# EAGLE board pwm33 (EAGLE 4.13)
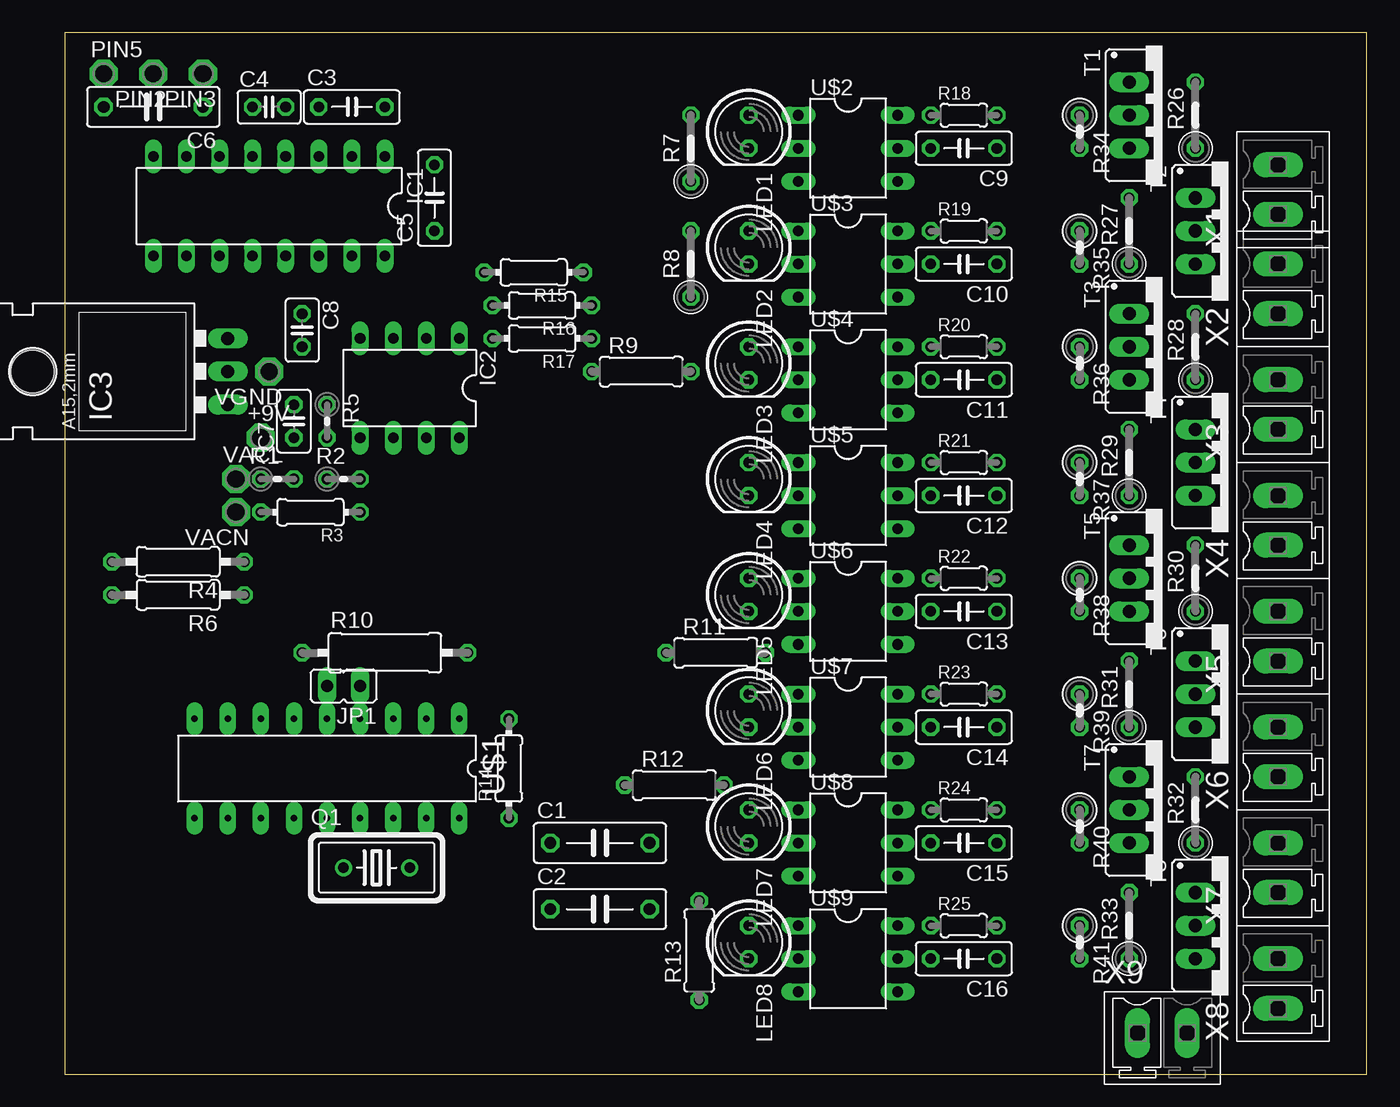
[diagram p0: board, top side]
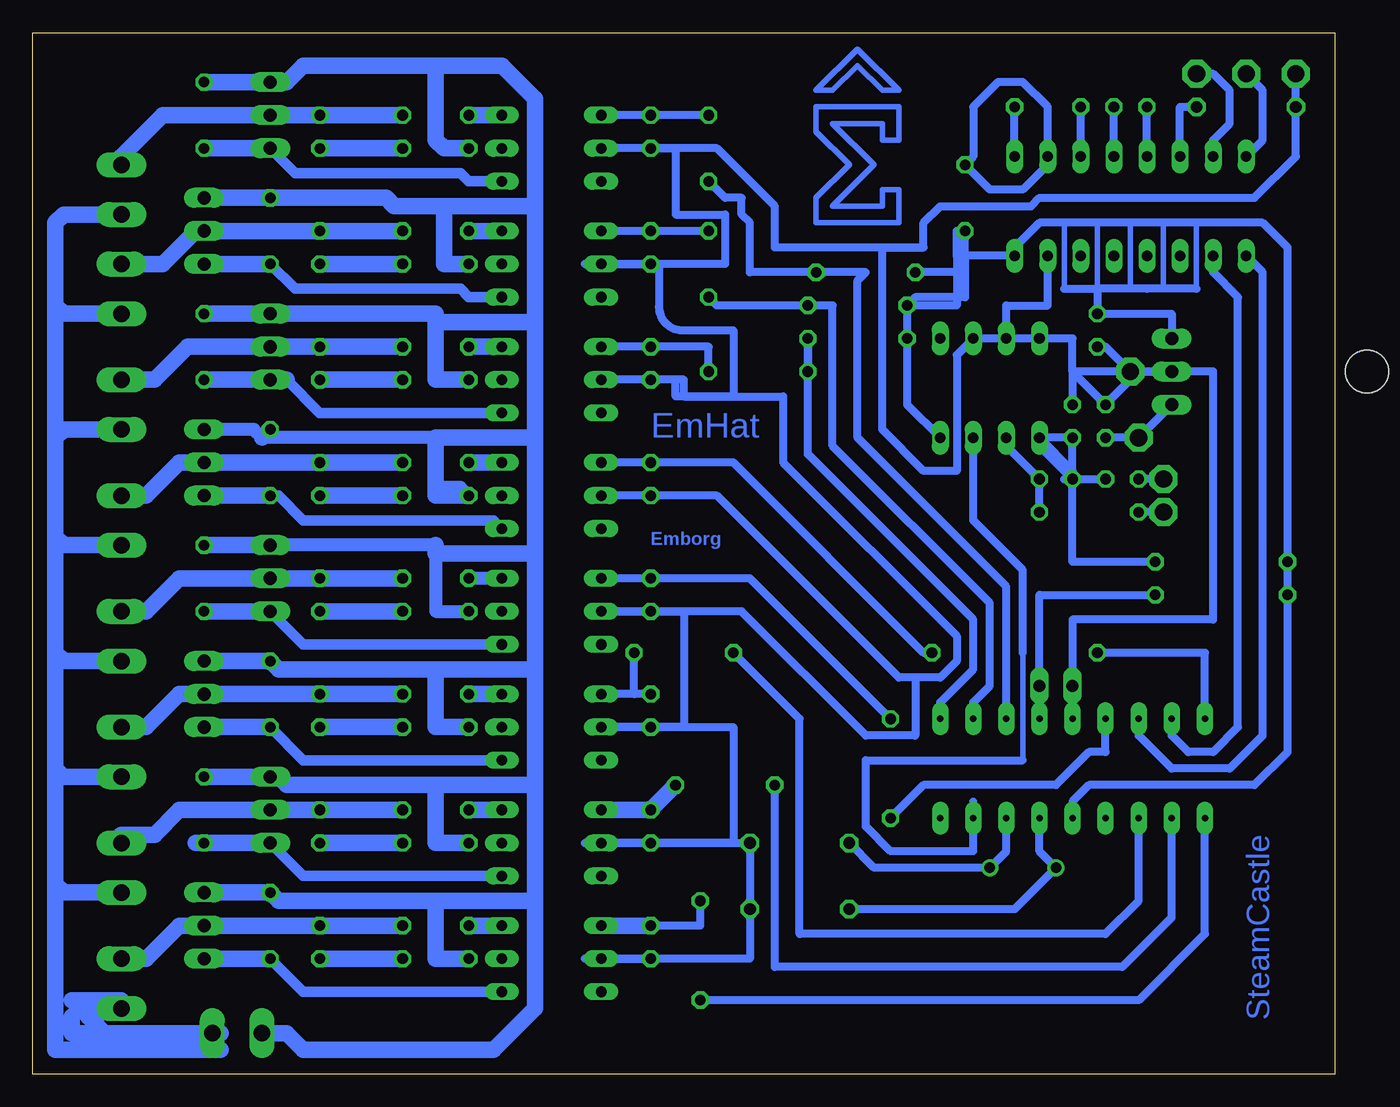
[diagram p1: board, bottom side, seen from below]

Size 100 x 80 mm. Coordinates in mm from the lower left corner, seen from the top.
Outline: 0,0 100,0 100,80 0,80 0,0
Copper layers (1*16): Top 0.035mm / dielectric 1.5mm / Bottom 0.035mm
Design rules "default": minimum track width 10mil, minimum drill 16mil, track to track 8mil, track to pad 8mil, pad to pad 8mil, via to via 8mil, smd to smd 8mil, copper to edge 40mil, drill to drill 8mil, minimum pad ring 10mil, minimum via ring 8mil, stop-mask expansion 4mil, vias tented up to drill 0mil, thermal gap 10mil

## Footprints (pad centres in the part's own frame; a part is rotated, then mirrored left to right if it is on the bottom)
P1-13 = drill 1.321 pad 2.159 octagon: 1 0,0
C075-032X103 = drill 0.914 octagon: 1 -3.81,0; 2 3.81,0
C050-025X075 = drill 0.813 octagon: 1 -2.54,0; 2 2.54,0
C025-025X050 = drill 0.813 octagon: 1 -1.27,0; 2 1.27,0
DIL16 = drill 0.813 long: 1 -8.89,-3.81; 2 -6.35,-3.81; 3 -3.81,-3.81; 4 -1.27,-3.81; 5 1.27,-3.81; 6 3.81,-3.81; 7 6.35,-3.81; 8 8.89,-3.81; 9 8.89,3.81; 10 6.35,3.81; 11 3.81,3.81; 12 1.27,3.81; 13 -1.27,3.81; 14 -3.81,3.81; 15 -6.35,3.81; 16 -8.89,3.81
DIL08 = drill 0.813 long: 1 -3.81,-3.81; 2 -1.27,-3.81; 3 1.27,-3.81; 4 3.81,-3.81; 5 3.81,3.81; 6 1.27,3.81; 7 -1.27,3.81; 8 -3.81,3.81
78XXL = drill 1.016 long: GND 0,-3.81; IN -2.54,-3.81; OUT 2.54,-3.81 | hole 3.302: 0,11.176
JP1 = drill 0.914 long: 1 0,-1.27; 2 0,1.27
LED5MM = drill 0.813 octagon: A -1.27,0; K 1.27,0
HC18U-V = drill 0.813 round: 1 -2.54,0; 2 2.54,0
0204V = drill 0.813 octagon: 1 -1.27,0; 2 1.27,0
0204/7 = drill 0.813 octagon: 1 -3.81,0; 2 3.81,0
0207/10 = drill 0.813 octagon: 1 -5.08,0; 2 5.08,0
0207/5V = drill 0.813 octagon: 1 -2.54,0; 2 2.54,0
0207/7 = drill 0.813 octagon: 1 -3.81,0; 2 3.81,0
0309/12 = drill 0.813 octagon: 1 -6.35,0; 2 6.35,0
0204/5 = drill 0.813 octagon: 1 -2.54,0; 2 2.54,0
0207/2V = drill 0.813 octagon: 1 -1.27,0; 2 1.27,0
TO220DS = drill 1.016 long: A1 -2.54,-2.54; A2 0,-2.54; G 2.54,-2.54
DIL18 = drill 0.5 pad 1.27 long: 1 -10.16,-3.81; 2 -7.62,-3.81; 3 -5.08,-3.81; 4 -2.54,-3.81; 5 0,-3.81; 6 2.54,-3.81; 7 5.08,-3.81; 8 7.62,-3.81; 9 10.16,-3.81; 10 10.16,3.81; 11 7.62,3.81; 12 5.08,3.81; 13 2.54,3.81; 14 0,3.81; 15 -2.54,3.81; 16 -5.08,3.81; 17 -7.62,3.81; 18 -10.16,3.81
DIL06 = drill 0.813 long: 1 -2.54,-3.81; 2 0,-3.81; 3 2.54,-3.81; 4 2.54,3.81; 5 0,3.81; 6 -2.54,3.81
MCV2 = drill 1.27 pad 1.905 long: 1 -1.905,0; 2 1.905,0

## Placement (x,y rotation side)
+9V  PTR1PAD1-13  [P1-13]  15.08,48.89 0 top
C1  20pF  [C075-032X103]  41.11,17.77 0 top
C2  20pF  [C075-032X103]  41.11,12.7 0 top
C3  1uF  [C050-025X075]  22.06,74.29 0 top
C4  1uF  [C025-025X050]  15.71,74.29 0 top
C5  1uF  [C050-025X075]  28.41,67.3 90 top
C6  1uF  [C075-032X103]  6.82,74.29 180 top
C7  1uF  [C025-025X050]  17.61,50.16 90 top
C8  1uF  [C025-025X050]  18.25,57.15 270 top
C9  0,01uF_400V  [C050-025X075]  69.05,71.11 180 top
C10  0,01uF_400V  [C050-025X075]  69.05,62.23 180 top
C11  0,01uF_400V  [C050-025X075]  69.05,53.34 180 top
C12  0,01uF_400V  [C050-025X075]  69.05,44.45 180 top
C13  0,01uF_400V  [C050-025X075]  69.05,35.55 180 top
C14  0,01uF_400V  [C050-025X075]  69.05,26.66 180 top
C15  0,01uF_400V  [C050-025X075]  69.05,17.77 180 top
C16  0,01uF_400V  [C050-025X075]  69.05,8.89 180 top
IC1  MAX232  [DIL16]  15.71,66.67 180 top
IC2  LM358N  [DIL08]  26.5,52.7 180 top
IC3  [78XXL]  8.73,53.97 90 top
JP1  [JP1]  21.42,29.84 90 top
LED1  [LED5MM]  52.54,72.38 270 top
LED2  [LED5MM]  52.54,63.5 270 top
LED3  [LED5MM]  52.54,54.61 270 top
LED4  [LED5MM]  52.54,45.72 270 top
LED5  [LED5MM]  52.54,36.83 270 top
LED6  [LED5MM]  52.54,27.93 270 top
LED7  [LED5MM]  52.54,19.04 270 top
LED8  [LED5MM]  52.54,10.16 270 top
PIN2  PTR1PAD1-13  [P1-13]  6.82,76.83 180 top
PIN3  PTR1PAD1-13  [P1-13]  10.63,76.83 180 top
PIN5  PTR1PAD1-13  [P1-13]  3.01,76.83 0 top
Q1  20Mhz  [HC18U-V]  23.96,15.87 0 top
R1  Aohm  [0204V]  16.34,45.72 0 top
R2  Bohm  [0204V]  21.42,45.72 0 top
R3  Aohm  [0204/7]  18.88,43.18 180 top
R4  5K  [0207/10]  8.73,39.37 180 top
R5  5K  [0204V]  20.15,50.16 270 top
R6  10K  [0207/10]  8.73,36.83 180 top
R7  240ohm  [0207/5V]  48.09,71.11 90 top
R8  240ohm  [0207/5V]  48.09,62.23 90 top
R9  240ohm  [0207/7]  44.28,53.97 0 top
R10  240ohm  [0309/12]  24.6,32.38 0 top
R11  240ohm  [0207/7]  50,32.38 0 top
R12  240ohm  [0207/7]  46.82,22.22 0 top
R13  240ohm  [0207/7]  48.73,9.52 90 top
R14  240ohm  [0204/7]  34.12,23.49 90 top
R15  10K  [0204/7]  36.03,61.59 180 top
R16  10K  [0204/7]  36.66,59.05 180 top
R17  10K  [0204/7]  36.66,56.51 180 top
R18  360ohm  [0204/5]  69.05,73.66 0 top
R19  360ohm  [0204/5]  69.05,64.77 0 top
R20  360ohm  [0204/5]  69.05,55.88 0 top
R21  360ohm  [0204/5]  69.05,46.98 0 top
R22  360ohm  [0204/5]  69.05,38.1 0 top
R23  360ohm  [0204/5]  69.05,29.2 0 top
R24  360ohm  [0204/5]  69.05,20.31 0 top
R25  360ohm  [0204/5]  69.05,11.43 0 top
R26  330ohm  [0207/5V]  86.83,73.66 90 top
R27  330ohm  [0207/5V]  81.75,64.77 90 top
R28  330ohm  [0207/5V]  86.83,55.88 90 top
R29  330ohm  [0207/5V]  81.75,46.98 90 top
R30  330ohm  [0207/5V]  86.83,38.1 90 top
R31  330ohm  [0207/5V]  81.75,29.2 90 top
R32  330ohm  [0207/5V]  86.83,20.31 90 top
R33  330ohm  [0207/5V]  81.75,11.43 90 top
R34  39ohm  [0207/2V]  77.94,72.38 270 top
R35  39ohm  [0207/2V]  77.94,63.5 270 top
R36  39ohm  [0207/2V]  77.94,54.61 270 top
R37  39ohm  [0207/2V]  77.94,45.72 270 top
R38  39ohm  [0207/2V]  77.94,36.83 270 top
R39  39ohm  [0207/2V]  77.94,27.93 270 top
R40  39ohm  [0207/2V]  77.94,19.04 270 top
R41  39ohm  [0207/2V]  77.94,10.16 270 top
T1  TIC225S  [TO220DS]  84.29,73.66 270 top
T2  TIC225S  [TO220DS]  89.37,64.77 270 top
T3  TIC225S  [TO220DS]  84.29,55.88 270 top
T4  TIC225S  [TO220DS]  89.37,46.98 270 top
T5  TIC225S  [TO220DS]  84.29,38.1 270 top
T6  TIC225S  [TO220DS]  89.37,29.2 270 top
T7  TIC225S  [TO220DS]  84.29,20.31 270 top
T8  TIC225S  [TO220DS]  89.37,11.43 270 top
U$1  PIC16F627I/P  [DIL18]  20.15,23.49 180 top
U$2  MOC3021M  [DIL06]  60.16,71.11 270 top
U$3  MOC3021M  [DIL06]  60.16,62.23 270 top
U$4  MOC3021M  [DIL06]  60.16,53.34 270 top
U$5  MOC3021M  [DIL06]  60.16,44.45 270 top
U$6  MOC3021M  [DIL06]  60.16,35.55 270 top
U$7  MOC3021M  [DIL06]  60.16,26.66 270 top
U$8  MOC3021M  [DIL06]  60.16,17.77 270 top
U$9  MOC3021M  [DIL06]  60.16,8.89 270 top
VACL  PTR1PAD1-13  [P1-13]  13.17,45.72 0 top
VACN  PTR1PAD1-13  [P1-13]  13.17,43.18 180 top
VGND  PTR1PAD1-13  [P1-13]  15.71,53.97 180 top
X1  MCV2  [MCV2]  93.18,67.94 90 top
X2  MCV2  [MCV2]  93.18,60.32 90 top
X3  MCV2  [MCV2]  93.18,51.43 90 top
X4  MCV2  [MCV2]  93.18,42.54 90 top
X5  MCV2  [MCV2]  93.18,33.65 90 top
X6  MCV2  [MCV2]  93.18,24.76 90 top
X7  MCV2  [MCV2]  93.18,15.87 90 top
X8  MCV2  [MCV2]  93.18,6.98 90 top
X9  MCV2  [MCV2]  84.29,3.17 0 top

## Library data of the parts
+9V PIN2 PIN3 PIN5 VACL VACN VGND = testpad
C1-C16 R1-R41 = rcl
IC1 = maxim
IC2 = linear
IC3 = v-reg
JP1 = jumper
LED1-LED8 = led
Q1 = crystal
T1-T8 = triac
U$1 = microchip-4
U$2-U$9 = optocoupler
X1-X9 = con-phoenix-381_l

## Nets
N$1: C1.1 Q1.2 U$1.16
N$2: C2.1 Q1.1 U$1.15
N$3: +9V.1 C7.1 IC3.IN
N$4: C4.1 IC1.5
N$5: C4.2 IC1.4
N$6: C3.1 IC1.3
N$7: C3.2 IC1.1
N$8: C5.2 IC1.2
N$9: C6.1 IC1.6
N$10: R9.1 R17.1 U$1.1
N$11: IC2.6 R2.2 R3.1
N$12: IC2.7 U$1.17
N$13: IC2.5 R1.2 R2.1 R4.1 R5.2
N$14: IC1.9 U$1.7
N$15: IC1.10 U$1.8
N$16: R1.1 VACL.1
N$17: R3.2 VACN.1
N$18: R8.1 R16.1 U$1.2
N$19: R7.1 R15.1 U$1.3
N$20: IC1.8 PIN2.1
N$21: IC1.7 PIN3.1
N$22: R14.1 U$1.6
N$23: R10.1 U$1.9
N$24: R11.1 U$1.12
N$25: R12.1 U$1.11
N$26: R13.1 U$1.10
N$27: LED1.A R7.2 U$2.1
N$28: LED2.A R8.2 U$3.1
N$29: LED3.A R9.2 U$4.1
N$30: LED4.A R10.2 U$5.1
N$31: LED5.A R14.2 U$6.1
N$32: LED6.A R11.2 U$7.1
N$33: LED7.A R12.2 U$8.1
N$34: LED8.A R13.2 U$9.1
N$35: X1.1 X2.1 X3.1 X4.1 X5.1 X6.1 X7.1 X8.1 X9.2
N$36: JP1.1 R6.1 U$1.4
N$37: C9.1 R34.2
N$38: R18.1 U$2.6
N$39: R19.1 U$3.6
N$40: R20.1 U$4.6
N$41: R21.1 U$5.6
N$42: R22.1 U$6.6
N$43: R23.1 U$7.6
N$44: R24.1 U$8.6
N$45: R25.1 U$9.6
N$46: R18.2 R34.1 T1.A2 X1.2
N$47: R19.2 R35.1 T2.A2 X2.2
N$48: R20.2 R36.1 T3.A2 X3.2
N$49: R21.2 R37.1 T4.A2 X4.2
N$50: R22.2 R38.1 T5.A2 X5.2
N$51: R23.2 R39.1 T6.A2 X6.2
N$52: R24.2 R40.1 T7.A2 X7.2
N$53: R25.2 R41.1 T8.A2 X8.2
N$54: R26.1 T1.G U$2.4
N$55: R27.1 T2.G U$3.4
N$56: R28.1 T3.G U$4.4
N$57: R29.1 T4.G U$5.4
N$58: R30.1 T5.G U$6.4
N$59: R31.1 T6.G U$7.4
N$60: R32.1 T7.G U$8.4
N$61: R33.1 T8.G U$9.4
N$62: C9.2 C10.2 C11.2 C12.2 C13.2 C14.2 C15.2 C16.2 R26.2 R27.2 R28.2 R29.2 R30.2 R31.2 R32.2 R33.2 T1.A1 T2.A1 T3.A1 T4.A1 T5.A1 T6.A1 T7.A1 T8.A1 X9.1
N$70: C10.1 R35.2
N$71: C11.1 R36.2
N$72: C12.1 R37.2
N$73: C13.1 R38.2
N$74: C14.1 R39.2
N$75: C15.1 R40.2
N$76: C16.1 R41.2
V+: C5.1 C8.1 IC1.16 IC2.8 IC3.OUT R4.2 R6.2 R15.2 R16.2 R17.2 U$1.14
V-: C1.2 C2.2 C6.2 C7.2 C8.2 IC1.15 IC2.2 IC2.3 IC2.4 IC3.GND JP1.2 LED1.K LED2.K LED3.K LED4.K LED5.K LED6.K LED7.K LED8.K PIN5.1 R5.1 U$1.5 U$2.2 U$3.2 U$4.2 U$5.2 U$6.2 U$7.2 U$8.2 U$9.2 VGND.1

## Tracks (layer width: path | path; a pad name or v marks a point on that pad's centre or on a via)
N$1
  Bottom 0.61: U$1.16 25.23,17.14 Q1.2 35.39,15.87 C1.1
N$2
  Bottom 0.61: C2.1 24.6,12.7 Q1.1 22.7,17.14 U$1.15
N$3
  Bottom 0.61: C7.1 +9V.1 IC3.IN
N$4
  Bottom 0.61: IC1.5 C4.1
N$5
  Bottom 0.61: IC1.4 C4.2
N$6
  Bottom 0.61: IC1.3 C3.1
N$7
  Bottom 0.61: IC1.1 C3.2
N$8
  Bottom 0.61: 23.96,67.94 26.5,67.94 C5.2 27.77,70.48 27.77,74.29 25.87,76.19 23.96,76.19 22.06,74.29 IC1.2 22.06,69.84 23.96,67.94
N$9
  Bottom 0.61: C6.1 11.9,74.29 IC1.6
N$10
  Bottom 0.61: R9.1 R17.1 40.48,47.62 27.77,34.92 27.77,31.11 30.31,28.57 U$1.1
N$11
  Bottom 0.61: R3.1 R2.2 25.23,48.26 IC2.6
N$12
  Bottom 0.406: 23.96,24.12 23.96,32.38
  Bottom 0.61: IC2.7 27.77,42.54 23.96,38.73 23.96,32.38 | 27.77,20.95 U$1.17 27.77,17.14 34.12,17.14 36.03,19.04 36.03,24.12 23.96,24.12
N$13
  Bottom 0.61: IC2.5 R5.2 20.15,46.35 | IC2.5 22.7,48.26 R2.1 | R4.1 20.15,39.37 R2.1 | R2.1 R1.2 | R2.1 20.79,45.72 | 20.15,46.35 IC2.5 | R2.1 20.15,46.35
N$14
  Bottom 0.61: U$1.7 15.08,26.03 12.54,23.49 8.09,23.49 5.55,26.03 5.55,61.59 IC1.9
N$15
  Bottom 0.61: U$1.8 12.54,26.03 11.27,24.76 9.36,24.76 7.46,26.66 7.46,59.69 9.36,61.59 IC1.10
N$16
  Bottom 0.61: VACL.1 R1.1
N$17
  Bottom 0.61: VACN.1 R3.2
N$18
  Bottom 0.61: R8.1 47.46,59.05 R16.1 38.57,59.05 38.57,48.26 26.5,36.19 26.5,29.84 27.77,28.57 U$1.2
N$19
  Bottom 0.61: U$1.3 25.23,37.46 36.66,48.89 36.66,60.96 36.03,61.59 R15.1 44.92,61.59 44.92,65.4 45.55,66.03 45.55,67.3 46.82,67.3 R7.1
N$20
  Bottom 0.61: PIN2.1 5.55,75.56 5.55,71.75 IC1.8
N$21
  Bottom 0.61: IC1.7 9.36,71.75 8.09,73.02 8.09,75.56 9.36,76.83 PIN3.1
N$22
  Bottom 0.61: U$1.6 17.61,24.76 18.88,24.76 21.42,22.22 31.58,22.22 R14.1
N$23
  Bottom 0.61: R10.1 10,32.38 U$1.9
N$24
  Bottom 0.61: R11.1 41.11,27.3 41.11,10.79 17.61,10.79 15.08,13.33 U$1.12
N$25
  Bottom 0.61: U$1.11 12.54,12.06 16.34,8.25 43.02,8.25 R12.1
N$26
  Bottom 0.61: U$1.10 10,10.79 15.08,5.71 R13.1
N$27
  Bottom 0.61: R7.2 LED1.A | LED1.A U$2.1 LED1.A
N$28
  Bottom 0.61: R8.2 LED2.A | LED2.A U$3.1 LED2.A
N$29
  Bottom 0.61: LED3.A 48.09,55.88 R9.2 | LED3.A U$4.1 LED3.A
N$30
  Bottom 0.61: R10.2 31.58,32.38 46.19,46.98 LED4.A U$5.1
N$31
  Bottom 0.61: U$6.1 LED5.A 44.92,38.1 R14.2
N$32
  Bottom 0.61: U$7.1 LED6.A 53.81,29.2 R11.2
N$33
  Bottom 1.27: U$8.1 LED7.A R12.2
N$34
  Bottom 0.61: R13.2 48.73,11.43 LED8.A
  Bottom 1.27: LED8.A U$9.1
N$35
  Bottom 1.27: X1.1 97.62,66.03 98.26,65.4 98.26,59.05 | 98.26,14.6 98.26,1.9 86.83,1.9 | 98.26,14.6 98.26,23.49 | 98.26,23.49 98.26,32.38 | 98.26,32.38 98.26,41.27 | 98.26,41.27 98.26,48.89 | 98.26,48.89 98.26,59.05 | 86.83,1.9 85.56,3.17 X9.2 | X9.2 96.99,3.17 96.99,4.44 95.72,5.71 | 95.72,5.71 96.99,5.71 | 95.72,5.71 93.18,5.71 | X7.1 97.62,13.97 98.26,14.6 | X6.1 97.62,22.86 98.26,23.49 | X5.1 97.62,31.74 98.26,32.38 | X4.1 97.62,40.64 98.26,41.27 | X3.1 97.62,49.53 98.26,48.89 | X2.1 97.62,58.41 98.26,59.05 | X9.2 94.45,3.17 95.72,4.44 95.08,4.44 94.45,5.08 X8.1 | X9.2 86.19,2.54 85.56,1.9 86.83,1.9
N$36
  Bottom 0.61: U$1.4 JP1.1 22.7,36.83 R6.1
N$37
  Bottom 1.27: C9.1 R34.2
N$38
  Bottom 1.27: U$2.6 R18.1
N$39
  Bottom 1.27: U$3.6 R19.1
N$40
  Bottom 1.27: U$4.6 R20.1
N$41
  Bottom 1.27: U$5.6 R21.1
N$42
  Bottom 1.016: U$6.6 R22.1
N$43
  Bottom 1.27: U$7.6 R23.1
N$44
  Bottom 1.27: U$8.6 R24.1
N$45
  Bottom 1.27: U$9.6 R25.1
N$46
  Bottom 1.27: X1.2 93.18,70.48 90,73.66 T1.A2 R34.1 R18.2
N$47
  Bottom 1.27: 93.81,62.23 X2.2 90,62.23 87.47,64.77 T2.A2 78.58,64.77 | 78.58,64.77 R35.1 | R19.2 78.58,64.77
N$48
  Bottom 1.27: R20.2 R36.1 | R36.1 T3.A2 | X3.2 90.64,53.34 88.1,55.88 T3.A2 | R36.1 T3.A2
N$49
  Bottom 1.27: 93.81,44.45 X4.2 91.28,44.45 88.73,46.98 T4.A2 | R21.2 R37.1 | R37.1 T4.A2 | R37.1 T4.A2
N$50
  Bottom 1.27: 85.56,38.1 T5.A2 R38.1 | 85.56,38.1 88.73,38.1 91.28,35.55 X5.2 93.81,35.55 | R22.2 R38.1 | R38.1 85.56,38.1
N$51
  Bottom 1.27: 93.81,26.66 X6.2 91.28,26.66 88.73,29.2 T6.A2 R39.1 | R39.1 R23.2 R39.1
N$52
  Bottom 1.27: R40.1 R24.2 R40.1 | R40.1 T7.A2 88.73,20.31 90.64,18.41 93.18,18.41 X7.2
N$53
  Bottom 1.27: R25.2 R41.1 T8.A2 88.73,11.43 91.28,8.89 X8.2
N$54
  Bottom 0.813: T1.G 79.84,69.21 67.14,69.21 66.51,68.57 U$2.4
  Bottom 1.27: T1.G R26.1
N$55
  Bottom 0.813: R27.1 79.84,60.32 67.14,60.32 66.51,59.69 U$3.4
  Bottom 1.27: R27.1 T2.G
N$56
  Bottom 0.813: U$4.4 77.94,50.8 80.48,53.34
  Bottom 1.27: 80.48,53.34 T3.G R28.1
N$57
  Bottom 0.61: 81.11,44.45 R29.1
  Bottom 0.813: U$5.4 64.61,42.54 79.21,42.54 81.11,44.45
  Bottom 1.27: R29.1 T4.G
N$58
  Bottom 0.813: T5.G 79.21,33.02 U$6.4
  Bottom 1.27: T5.G R30.1
N$59
  Bottom 0.61: R31.1 T6.G
  Bottom 0.813: R31.1 79.21,24.12 U$7.4
  Bottom 1.27: R31.1 T6.G
N$60
  Bottom 0.813: T7.G 79.21,15.24 U$8.4
  Bottom 1.27: T7.G R32.1 87.47,17.77
N$61
  Bottom 0.61: R33.1 T8.G
  Bottom 0.813: U$9.4 79.21,6.34 R33.1
  Bottom 1.27: R33.1 T8.G
N$62
  Bottom 0.61: 61.43,48.89 62.06,48.89 | 68.41,66.67 68.41,66.03
  Bottom 1.016: C12.2 67.14,45.08 69.05,45.08 | 69.05,48.89 82.39,48.89 83.02,49.53 T4.A1 | 69.05,40.64 T5.A1 | 69.05,40 69.05,35.55 C13.2
  Bottom 1.27: X9.1 80.48,3.17 79.21,1.9 64.61,1.9 61.43,5.08 61.43,13.33 | 61.43,57.78 61.43,66.67 | 61.43,22.22 61.43,31.11 | 61.43,31.11 61.43,40 | 61.43,40 61.43,48.89 61.43,57.78 | 61.43,13.33 61.43,22.22 | R26.2 T1.A1 80.48,76.19 79.21,77.46 69.05,77.46 | 69.05,77.46 63.97,77.46 61.43,74.92 61.43,66.67 | 80.48,67.3 R27.2 T2.A1 72.86,67.3 72.22,66.67 68.41,66.67 61.43,66.67 | 69.05,58.41 69.05,53.34 C11.2 | 68.41,66.03 68.41,62.23 C10.2 | R28.2 T3.A1 69.05,58.41 | T5.A1 R30.2 | R31.2 T6.A1 R31.2 | T7.A1 R32.2 81.11,22.86 80.48,22.22 69.05,22.22 | T8.A1 R33.2 81.11,13.33 69.05,13.33 | 69.05,22.22 69.05,17.77 C15.2 | R31.2 81.11,31.11 69.05,31.11 | 82.39,48.89 R29.2 | 61.43,57.78 69.05,57.78 69.05,58.41 | 62.06,48.89 69.05,48.89 69.05,44.45 C12.2 | C14.2 69.05,26.66 69.05,31.11 | 61.43,31.11 69.05,31.11 | 61.43,22.22 69.05,22.22 | C16.2 69.05,8.89 69.05,13.33 | 61.43,13.33 69.05,13.33 | C9.2 68.41,71.11 69.05,71.75 69.05,77.46 | 69.05,40.64 69.05,40 61.43,40
N$65
  Bottom 0.406: 39.84,65.4 39.84,67.3 37.3,69.84 39.84,72.38 39.84,74.29 33.49,74.29 33.49,71.75 34.76,71.75 34.76,73.02 38.57,73.02 35.39,69.84 38.57,66.67 34.76,66.67 34.76,67.94 33.49,67.94 33.49,65.4 39.84,65.4
N$66
  Bottom 0.406: 33.49,75.56 36.66,78.73 39.84,75.56 38.57,75.56 36.66,77.46 34.76,75.56 33.49,75.56
N$70
  Bottom 1.27: C10.1 R35.2
N$71
  Bottom 1.27: C11.1 R36.2
N$72
  Bottom 1.27: C12.1 R37.2
N$73
  Bottom 1.27: C13.1 R38.2
N$74
  Bottom 1.27: C14.1 R39.2
N$75
  Bottom 1.27: C15.1 R40.2
N$76
  Bottom 1.27: C16.1 R41.2
V+
  Bottom 0.406: 20.79,60.32 20.79,65.4 13.17,65.4 13.17,60.32 14.44,60.32 15.71,60.32 15.71,65.4 18.25,65.4 18.25,60.32 | 10.63,65.4 10.63,60.32
  Bottom 0.61: 29.04,62.86 29.04,64.77 C5.1 28.41,62.86 | 29.04,62.86 29.04,61.59 R15.2 | R16.2 32.22,59.69 28.41,59.69 28.41,62.86 | 28.41,62.86 IC1.16 24.6,63.5 22.7,65.4 20.79,65.4 10.63,65.4 5.55,65.4 3.64,63.5 R4.2 | 28.41,62.86 29.04,62.86 | 29.04,62.86 29.04,59.05 R16.2 | IC3.OUT 12.54,58.41 C8.1 18.25,60.32 | 10.63,60.32 14.44,60.32 18.25,60.32 | 20.79,60.32 18.25,60.32 | U$1.14 20.15,20.95 18.88,22.22 6.18,22.22 3.64,24.76 R6.2 | R6.2 R4.2 | 32.85,58.41 R17.2 | R16.2 32.85,58.41 | 32.85,58.41 32.85,51.43 IC2.8 | R6.2 R4.2 | R6.2 R4.2 | R6.2 R4.2
V-
  Bottom 0.61: U$1.5 JP1.2 20.15,34.92 9.36,34.92 9.36,53.97 20.15,53.97 | LED1.K U$2.2 | LED1.K 50.63,71.11 50.63,66.03 46.82,66.03 46.82,62.23 57.62,62.23 | 57.62,62.23 51.91,62.23 51.91,58.94 arc-90 50.11,57.15 46.19,57.15 46.19,52.07 50,52.07 | 50,52.07 50.63,52.07 50.63,53.34 | 50.63,53.34 LED3.K | 50.63,53.34 50,53.34 50,52.07 | 50,52.07 42.38,52.07 42.38,46.98 29.04,33.65 29.04,31.74 30.31,30.47 32.22,30.47 | 32.22,30.47 33.49,30.47 47.46,44.45 LED4.K | LED4.K U$5.2 | U$6.2 50,35.55 50,26.66 U$7.2 | U$7.2 46.19,26.66 46.19,17.77 | 46.19,17.77 57.62,17.77 | 57.62,17.77 C1.2 | C1.2 44.92,8.89 U$9.2 | U$9.2 LED8.K | 57.62,17.77 U$8.2 LED7.K 46.19,17.77 | U$7.2 LED6.K | U$6.2 LED5.K | LED4.K U$5.2 | LED3.K U$4.2 LED3.K | LED2.K U$3.2 57.62,62.23 | U$9.2 57.62,8.89 | C6.2 PIN5.1 C6.2 | LED1.K U$2.2 | LED1.K U$2.2 | VGND.1 IC3.GND | VGND.1 15.71,53.34 C7.2 20.15,53.97 | VGND.1 17.61,55.88 C8.2 | 20.15,53.97 20.15,56.51 IC2.4 | IC2.4 IC2.3 | IC2.3 IC2.2 29.04,55.24 29.04,46.35 31.58,46.35 34.76,49.53 34.76,63.5 31.58,63.5 | IC2.3 25.23,59.05 22.06,59.05 IC1.15 | 46.19,17.77 C1.2 | C1.2 C2.2 | 20.15,53.97 R5.1 | IC2.4 IC2.3 | LED1.K 47.46,71.11 43.02,66.67 43.02,63.5 31.58,63.5 | C6.2 3.01,70.48 6.18,67.3 22.7,67.3 23.33,66.67 30.31,66.67 31.58,65.4 31.58,63.5 | U$6.2 45.55,35.55 36.03,26.03 32.22,26.03 32.22,30.47 | LED4.K U$5.2

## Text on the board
Bottom: EmHat | Emborg | SteamCastle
